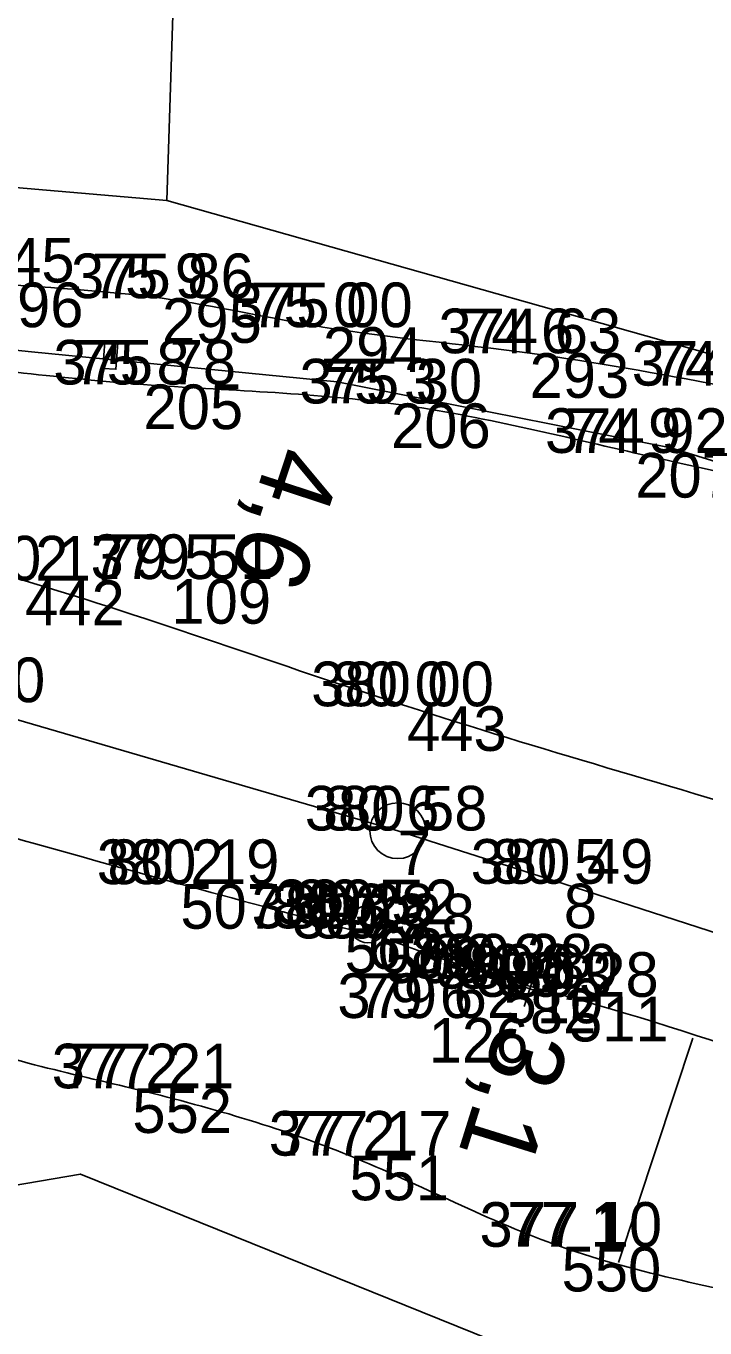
# Model space of a CAD drawing. Extents: x -514509 to -512782, y -1144610 to -1143439.
# Drawn here: x -513035.93 to -513017.7, y -1143617.66 to -1143582.66 of the extents above; entities that cross this region are included whole.
import ezdxf

# ---------------------------------------------------------------- set-up
doc = ezdxf.new("R2010")
doc.units = 0
for name, color, linetype in [('Vrstva 1', 7, 'Continuous'), ('Vrstva 10', 7, 'Continuous'), ('Vrstva 11', 7, 'Continuous'), ('Vrstva 12', 7, 'Continuous'), ('Vrstva 14', 7, 'Continuous'), ('Vrstva 57', 7, 'Continuous'), ('Vrstva 58', 7, 'Continuous'), ('Vrstva 59', 7, 'Continuous'), ('Vrstva 6', 7, 'Continuous'), ('Vrstva 60', 7, 'Continuous'), ('Vrstva 8', 7, 'Continuous')]:
    doc.layers.add(name, color=color, linetype=linetype)

msp = doc.modelspace()

# ---------------------------------------------------------------- linework, layer by layer
at = {"layer": 'Vrstva 1'}
msp.add_lwpolyline([(-513220.491, -1143575.228), (-513193.623, -1143570.982), (-513176.915, -1143569.129), (-513155.694, -1143568.05), (-513138.074, -1143568.989), (-513122.982, -1143570.739), (-513098.68, -1143574.346), (-513082.799, -1143577.731), (-513077.892, -1143579.384), (-513072.257, -1143581.789), (-513063.773, -1143586.163), (-513056.631, -1143588.823), (-513045.948, -1143590.353), (-513035.79, -1143591.42), (-513027.577, -1143592.226), (-513018.616, -1143594.003), (-513003.093, -1143598.799), (-512994.741, -1143602.979), (-512987.23, -1143608.317)], dxfattribs=at)
at = {"layer": 'Vrstva 10'}
for points in [[(-513082.58, -1143574.42), (-513049.36, -1143585.88), (-513032.15, -1143587.352), (-513013.645, -1143592.585), (-512996.08, -1143600.301), (-512976.442, -1143595.705), (-512976.456, -1143612.872), (-512962.931, -1143616.56), (-512954.194, -1143606.538), (-512930.452, -1143592.642), (-512928.362, -1143585.895), (-512925.699, -1143603.347)], [(-513082.58, -1143574.42), (-513049.36, -1143585.88), (-513032.15, -1143587.352), (-513013.645, -1143592.585), (-512996.08, -1143600.301), (-512976.442, -1143595.705), (-512976.456, -1143612.872), (-512962.931, -1143616.56), (-512954.194, -1143606.538), (-512930.452, -1143592.642), (-512928.362, -1143585.895), (-512925.699, -1143603.347)], [(-512782.341, -1143656.666), (-512796.89, -1143661.893), (-512815.309, -1143658.506), (-512846.358, -1143662.813), (-512847.692, -1143673.887), (-512850.552, -1143675.414), (-512874.542, -1143673.507), (-512907.663, -1143668.822), (-512937.442, -1143663.927), (-512942.033, -1143670.511), (-512944.784, -1143662.787), (-512958.978, -1143654.892), (-512977.284, -1143642.016), (-512997.25, -1143628.575), (-513034.474, -1143613.524), (-513050.89, -1143616.331), (-513050.251, -1143607.386), (-513065.331, -1143600.696), (-513084.436, -1143602.206), (-513086.215, -1143618.123), (-513093.877, -1143618.167), (-513107.772, -1143623.787)], [(-512782.341, -1143656.666), (-512796.89, -1143661.893), (-512815.309, -1143658.506), (-512846.358, -1143662.813), (-512847.692, -1143673.887), (-512850.552, -1143675.414), (-512874.542, -1143673.507), (-512907.663, -1143668.822), (-512937.442, -1143663.927), (-512942.033, -1143670.511), (-512944.784, -1143662.787), (-512958.978, -1143654.892), (-512977.284, -1143642.016), (-512997.25, -1143628.575), (-513034.474, -1143613.524), (-513050.89, -1143616.331), (-513050.251, -1143607.386), (-513065.331, -1143600.696), (-513084.436, -1143602.206), (-513086.215, -1143618.123), (-513093.877, -1143618.167), (-513107.772, -1143623.787)], [(-513027.378, -1143606.917), (-513026.294, -1143607.192)], [(-513018.021, -1143609.869), (-513020.023, -1143615.905)]]:
    msp.add_lwpolyline(points, dxfattribs=at)
for points in [[(-512953.995, -1143613.026), (-512957.258, -1143613.803), (-512961.396, -1143614.272), (-512966.482, -1143614.31), (-512970.759, -1143614.088), (-512973.268, -1143613.625), (-512976.312, -1143612.767), (-512979.387, -1143610.931), (-512983.271, -1143608.165), (-512988.084, -1143604.174), (-512993.595, -1143600.71), (-512999.183, -1143597.931), (-513003.859, -1143595.565), (-513008.344, -1143594.112), (-513012.116, -1143593.309), (-513017.24, -1143592.33), (-513022.405, -1143591.458), (-513027.962, -1143590.755), (-513032.282, -1143589.984), (-513037.071, -1143589.561), (-513042.298, -1143588.932), (-513047.694, -1143588.089), (-513050.837, -1143587.38), (-513055.493, -1143585.813), (-513060.929, -1143584.042), (-513065.663, -1143582.489), (-513071.062, -1143580.47), (-513076.142, -1143578.183), (-513080.606, -1143576.177), (-513085.081, -1143574.916), (-513090.677, -1143573.538)], [(-512953.995, -1143613.026), (-512957.258, -1143613.803), (-512961.396, -1143614.272), (-512966.482, -1143614.31), (-512970.759, -1143614.088), (-512973.268, -1143613.625), (-512976.312, -1143612.767), (-512979.387, -1143610.931), (-512983.271, -1143608.165), (-512988.084, -1143604.174), (-512993.595, -1143600.71), (-512999.183, -1143597.931), (-513003.859, -1143595.565), (-513008.344, -1143594.112), (-513012.116, -1143593.309), (-513017.24, -1143592.33), (-513022.405, -1143591.458), (-513027.962, -1143590.755), (-513032.282, -1143589.984), (-513037.071, -1143589.561), (-513042.298, -1143588.932), (-513047.694, -1143588.089), (-513050.837, -1143587.38), (-513055.493, -1143585.813), (-513060.929, -1143584.042), (-513065.663, -1143582.489), (-513071.062, -1143580.47), (-513076.142, -1143578.183), (-513080.606, -1143576.177), (-513085.081, -1143574.916), (-513090.677, -1143573.538)], [(-513094.522, -1143585.424), (-513085.972, -1143586.813), (-513077.096, -1143588.391), (-513066.158, -1143590.465), (-513056.46, -1143592.544), (-513046.346, -1143594.887), (-513035.955, -1143597.575), (-513025.704, -1143600.949), (-513014.943, -1143604.21), (-513004.729, -1143607.491)], [(-513045.435, -1143590.979), (-513039.213, -1143591.629), (-513032.779, -1143592.299), (-513026.133, -1143592.81), (-513019.57, -1143594.143), (-513014.993, -1143595.23), (-513009.333, -1143597.099), (-513004.427, -1143598.943), (-513000.195, -1143600.648), (-512995.465, -1143603.755), (-512990.482, -1143606.95), (-512986.481, -1143609.695), (-512982.688, -1143612.309), (-512979.1, -1143614.259), (-512976.081, -1143615.456), (-512973.855, -1143616.04), (-512971.299, -1143616.182), (-512967.877, -1143616.452), (-512963.669, -1143616.372), (-512959.668, -1143616.236), (-512956.333, -1143615.735)], [(-513045.435, -1143590.979), (-513039.213, -1143591.629), (-513032.779, -1143592.299), (-513026.133, -1143592.81), (-513019.57, -1143594.143), (-513014.993, -1143595.23), (-513009.333, -1143597.099), (-513004.427, -1143598.943), (-513000.195, -1143600.648), (-512995.465, -1143603.755), (-512990.482, -1143606.95), (-512986.481, -1143609.695), (-512982.688, -1143612.309), (-512979.1, -1143614.259), (-512976.081, -1143615.456), (-512973.855, -1143616.04), (-512971.299, -1143616.182), (-512967.877, -1143616.452), (-512963.669, -1143616.372), (-512959.668, -1143616.236), (-512956.333, -1143615.735)], [(-512979.1, -1143614.259), (-512982.688, -1143612.309), (-512986.481, -1143609.695), (-512990.482, -1143606.95), (-512995.465, -1143603.755), (-513000.195, -1143600.648), (-513004.427, -1143598.943), (-513009.333, -1143597.099), (-513014.993, -1143595.23), (-513019.57, -1143594.143), (-513026.133, -1143592.81), (-513032.779, -1143592.299), (-513039.213, -1143591.629), (-513045.435, -1143590.979)], [(-513091.48, -1143591.211), (-513084.48, -1143592.318), (-513076.865, -1143593.708), (-513068.286, -1143595.582), (-513060.823, -1143597.567), (-513051.402, -1143600.148), (-513042.167, -1143602.79), (-513031.788, -1143605.729), (-513027.378, -1143606.917)], [(-513026.294, -1143607.192), (-513023.106, -1143608.274), (-513021.348, -1143608.765), (-513009.307, -1143612.76), (-513002.468, -1143615.032), (-512991.168, -1143618.917), (-512983.493, -1143621.262), (-512973.793, -1143624.681), (-512967.617, -1143627.839), (-512965.38, -1143629.361), (-512962.646, -1143631.449), (-512962.312, -1143634.04), (-512962.624, -1143637.91), (-512963.109, -1143641.162), (-512963.893, -1143643.534), (-512965.524, -1143645.49)], [(-512993.539, -1143625.829), (-513001.654, -1143622.116), (-513007.851, -1143619.347), (-513015.061, -1143617.108), (-513021.554, -1143615.482), (-513027.253, -1143613.027), (-513033.075, -1143611.223), (-513038.613, -1143609.661), (-513041.608, -1143608.193)]]:
    msp.add_spline(points, degree=3, dxfattribs=at)
at = {"layer": 'Vrstva 12'}
for p, q in [((-513022.247, -1143608.068), (-513022.554, -1143609.019)), ((-513022.876, -1143608.39), (-513021.925, -1143608.697))]:
    msp.add_line(p, q, dxfattribs=at)
at = {"layer": 'Vrstva 14'}
msp.add_lwpolyline([(-513033.869, -1143591.867), (-513033.522, -1143591.892), (-513033.47, -1143591.176), (-513033.817, -1143591.151)], close=True, dxfattribs=at)
msp.add_circle((-513026.755, -1143606.808), 0.5, dxfattribs=at)
at = {"layer": 'Vrstva 6'}
msp.add_lwpolyline([(-513042.471, -1143599.582), (-513037.794, -1143600.839), (-513025.951, -1143604.295), (-513021.487, -1143605.723), (-513009.806, -1143609.501), (-513001.948, -1143612.085)], dxfattribs=at)
msp.add_circle((-513025.951, -1143604.295), 0.75, dxfattribs=at)
at = {"layer": 'Vrstva 60'}
for p, q in [((-513032.28, -1143589.98), (-513032.28, -1143589.98)), ((-513027.96, -1143590.76), (-513027.96, -1143590.76)), ((-513022.41, -1143591.46), (-513022.41, -1143591.46)), ((-513032.78, -1143592.3), (-513032.78, -1143592.3)), ((-513026.13, -1143592.81), (-513026.13, -1143592.81)), ((-513019.57, -1143594.14), (-513019.57, -1143594.14)), ((-513032.03, -1143597.53), (-513032.03, -1143597.53)), ((-513025.7, -1143600.95), (-513025.7, -1143600.95)), ((-513025.95, -1143604.29), (-513025.95, -1143604.29)), ((-513021.49, -1143605.72), (-513021.49, -1143605.72)), ((-513031.79, -1143605.73), (-513031.79, -1143605.73)), ((-513027.38, -1143606.92), (-513027.38, -1143606.92)), ((-513026.75, -1143606.81), (-513026.75, -1143606.81)), ((-513026.29, -1143607.19), (-513026.29, -1143607.19)), ((-513023.11, -1143608.27), (-513023.11, -1143608.27)), ((-513022.4, -1143608.54), (-513022.4, -1143608.54)), ((-513021.35, -1143608.76), (-513021.35, -1143608.76)), ((-513025.12, -1143609.33), (-513025.12, -1143609.33)), ((-513033.08, -1143611.22), (-513033.08, -1143611.22)), ((-513027.25, -1143613.03), (-513027.25, -1143613.03)), ((-513021.55, -1143615.48), (-513021.55, -1143615.48))]:
    msp.add_line(p, q, dxfattribs=at)
at = {"layer": 'Vrstva 8'}
msp.add_lwpolyline([(-513032.15, -1143587.352), (-513030.67, -1143541.436), (-513035.778, -1143485.469), (-513051.738, -1143489.896), (-513051.737, -1143485.623), (-513133.554, -1143509.18)], dxfattribs=at)

# ---------------------------------------------------------------- texts
at = {"layer": 'Vrstva 11'}
for s, rotation, p in [('4,6', 251.779, (-513029.314, -1143593.847)), ('3,1', 252.5959, (-513023.219, -1143609.382))]:
    msp.add_text(s, height=2, rotation=rotation, dxfattribs=at).set_placement(p)
at = {"layer": 'Vrstva 57'}
for s, p in [('75 9 ', (-513034.168, -1143589.98)), ('75 0 ', (-513029.908, -1143590.76)), ('74 6 ', (-513024.334, -1143591.46)), ('75 8 ', (-513034.663, -1143592.3)), ('74 4 ', (-513019.123, -1143592.33)), ('75 3 ', (-513028.013, -1143592.81)), ('74 9 ', (-513021.458, -1143594.14)), ('80 2 ', (-513037.92, -1143597.57)), ('79 5 ', (-513033.92, -1143597.53)), ('80 0 ', (-513027.726, -1143600.95)), ('80 6 ', (-513027.952, -1143604.29)), ('80 2 ', (-513033.75, -1143605.73)), ('80 5 ', (-513023.45, -1143605.72)), ('80 3 ', (-513029.34, -1143606.92)), ('80 5 ', (-513028.71, -1143606.81)), ('80 3 ', (-513028.25, -1143607.19)), ('80 3 ', (-513025.07, -1143608.27)), ('80 8 ', (-513024.36, -1143608.54)), ('80 3 ', (-513023.31, -1143608.76)), ('79 6 ', (-513027.051, -1143609.33)), ('77 2 ', (-513034.963, -1143611.22)), ('77 2 ', (-513029.133, -1143613.03)), ('77 1 ', (-513023.008, -1143615.48))]:
    msp.add_text(s, height=1.2, dxfattribs=at).set_placement(p)
at = {"layer": 'Vrstva 58'}
for s, p in [('376 45', (-513039.54, -1143589.56)), ('375 86', (-513034.726, -1143589.98)), ('375 00', (-513030.458, -1143590.76)), ('374 63', (-513024.856, -1143591.46)), ('375 78', (-513035.201, -1143592.3)), ('374 39', (-513019.664, -1143592.33)), ('375 30', (-513028.59, -1143592.81)), ('374 92', (-513021.994, -1143594.14)), ('380 17', (-513038.204, -1143597.57)), ('379 51', (-513034.203, -1143597.53)), ('380 70', (-513040.328, -1143600.84)), ('380 00', (-513028.276, -1143600.95)), ('380 58', (-513028.448, -1143604.29)), ('380 19', (-513034.038, -1143605.73)), ('380 49', (-513023.992, -1143605.72)), ('380 28', (-513029.878, -1143606.92)), ('380 52', (-513029.248, -1143606.81)), ('380 28', (-513028.788, -1143607.19)), ('380 28', (-513025.608, -1143608.27)), ('380 80', (-513024.938, -1143608.54)), ('380 28', (-513023.848, -1143608.76)), ('379 62', (-513027.572, -1143609.33)), ('377 21', (-513035.246, -1143611.22)), ('377 17', (-513029.416, -1143613.03)), ('377 10', (-513023.755, -1143615.48))]:
    msp.add_text(s, height=1.2, dxfattribs=at).set_placement(p)
at = {"layer": 'Vrstva 59'}
for s, p in [('296', (-513037.07, -1143590.76)), ('295', (-513032.28, -1143591.18)), ('294', (-513027.96, -1143591.96)), ('293', (-513022.41, -1143592.66)), ('205', (-513032.78, -1143593.5)), ('206', (-513026.13, -1143594.01)), ('207', (-513019.57, -1143595.34)), ('442', (-513035.96, -1143598.77)), ('109', (-513032.03, -1143598.73)), ('443', (-513025.7, -1143602.15)), ('7', (-513025.95, -1143605.49)), ('507', (-513031.79, -1143606.93)), ('8', (-513021.49, -1143606.92)), ('508', (-513027.38, -1143608.12)), ('60', (-513026.75, -1143608.01)), ('509', (-513026.29, -1143608.39)), ('510', (-513023.11, -1143609.47)), ('82', (-513022.4, -1143609.74)), ('511', (-513021.35, -1143609.96)), ('126', (-513025.12, -1143610.53)), ('552', (-513033.08, -1143612.42)), ('551', (-513027.25, -1143614.23)), ('550', (-513021.55, -1143616.68))]:
    msp.add_text(s, height=1.2, dxfattribs=at).set_placement(p)

doc.saveas('drawing.dxf')
